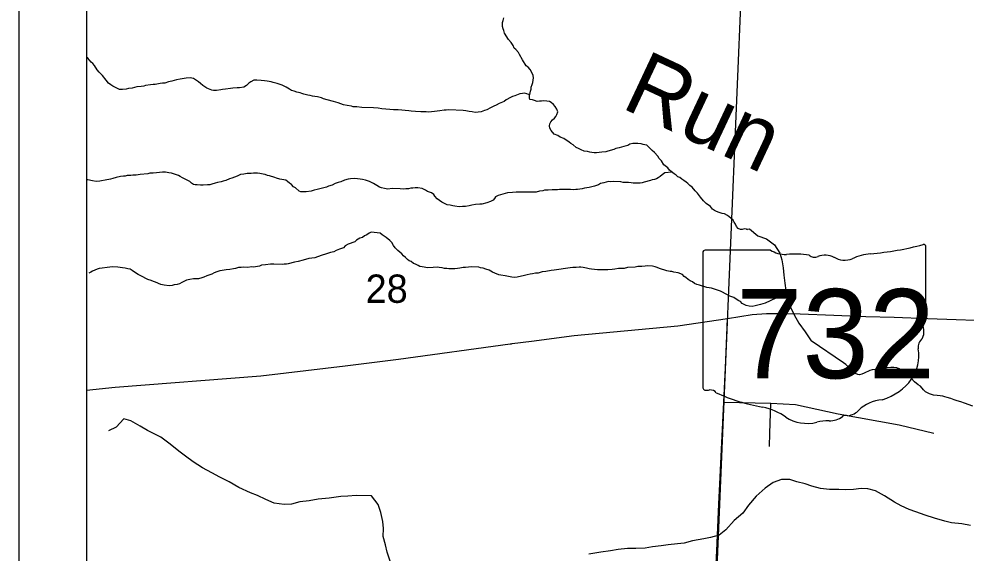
# Model space of a CAD drawing. Extents: x 0 to 34, y 0 to 22.
# Drawn here: x 2 to 3.4, y 18.922 to 19.712 of the extents above; entities that cross this region are included whole.
import ezdxf

# ---------------------------------------------------------------- set-up
doc = ezdxf.new("R2010")
doc.units = 0
for name, color, linetype in [('Default', 7, 'Continuous'), ('GM_X_City_Street', 7, 'Continuous'), ('GM_X_County_Road', 7, 'Continuous'), ('GM_X_Minor_River', 7, 'Continuous'), ('GM_X_Minor_River_Text', 7, 'Continuous'), ('GM_X_Section', 7, 'Continuous'), ('GM_X_Section_Text', 7, 'Continuous'), ('GM_X_State_Location', 7, 'Continuous'), ('GM_X_State_Route', 7, 'Continuous'), ('GM_X_State_Shield', 7, 'Continuous'), ('SH_Data', 7, 'Continuous')]:
    doc.layers.add(name, color=color, linetype=linetype)

msp = doc.modelspace()

# ---------------------------------------------------------------- linework, layer by layer
at = {"layer": 'Default'}
msp.add_lwpolyline([(6.0871, 20.9), (2.1, 20.9), (2.1, 17.8044), (2.8305, 17.7727), (2.976, 17.7664), (3.1037, 17.7609), (3.4544, 17.7458), (3.7662, 17.7368), (3.9904, 17.7296), (4.1165, 17.7286), (4.1238, 17.7269), (4.1354, 17.7264), (4.1969, 17.7246), (4.2769, 17.7222), (4.4203, 17.718), (4.506, 17.7155), (4.6237, 17.7121), (4.6735, 17.7102), (4.763, 17.7084), (4.9045, 17.7039), (4.98, 17.7015), (5.0396, 17.6997)], dxfattribs=at)
msp.add_lwpolyline([(2.1, 19.8201), (2.1, 18.8072), (3.0273, 18.7832), (3.0692, 19.7796)], close=True, dxfattribs=at)
at = {"layer": 'GM_X_City_Street'}
for points in [[(3.0419, 19.1453), (3.1112, 19.1437), (3.1478, 19.1417), (3.2111, 19.128), (3.301, 19.1116), (3.3521, 19.0995)], [(3.1095, 19.0796), (3.1098, 19.0993), (3.1106, 19.1136), (3.1112, 19.1437)]]:
    msp.add_lwpolyline(points, dxfattribs=at)
at = {"layer": 'GM_X_County_Road'}
msp.add_line((2.7281, 19.2315), (2.7291, 19.2317), dxfattribs=at)
for points in [[(2.7291, 19.2317), (2.7577, 19.2352), (2.8206, 19.2436), (2.9741, 19.2578), (3.0474, 19.269)], [(3.0474, 19.269), (3.0839, 19.2749), (3.1052, 19.2762), (3.124, 19.2763), (3.1547, 19.2758), (3.2047, 19.2738), (3.2517, 19.2718), (3.2939, 19.2706), (3.3433, 19.2687), (3.3854, 19.2673), (3.4132, 19.2664), (3.4438, 19.2649), (3.4835, 19.2641), (3.5284, 19.2621), (3.5555, 19.2612), (3.6227, 19.2594), (3.6633, 19.2574)], [(2.3952, 19.1886), (2.482, 19.1988), (2.5612, 19.2087), (2.726, 19.2313), (2.7281, 19.2315)], [(2.1, 19.163), (2.1423, 19.1675), (2.3574, 19.1842), (2.3952, 19.1886)]]:
    msp.add_lwpolyline(points, dxfattribs=at)
at = {"layer": 'GM_X_Minor_River'}
for points in [[(2.8237, 19.5216), (2.8192, 19.5256), (2.8159, 19.5276), (2.8132, 19.5296), (2.8054, 19.5348), (2.7998, 19.5369), (2.7964, 19.5393), (2.7911, 19.5414), (2.7867, 19.5469), (2.7846, 19.5504), (2.7843, 19.5535), (2.7848, 19.5569), (2.7864, 19.5595), (2.7888, 19.5628), (2.7915, 19.565), (2.7935, 19.5676), (2.7952, 19.5706), (2.7964, 19.5744), (2.795, 19.5782), (2.7925, 19.5821), (2.7903, 19.5853), (2.7866, 19.5884), (2.784, 19.5897), (2.7802, 19.5902), (2.7752, 19.5907), (2.7726, 19.5904), (2.7695, 19.5902), (2.7661, 19.5899), (2.7623, 19.5912), (2.7589, 19.592), (2.7551, 19.5926), (2.7548, 19.5952), (2.7549, 19.5983), (2.7558, 19.6024), (2.7559, 19.6051), (2.7571, 19.6081), (2.7572, 19.6108), (2.7585, 19.6149), (2.7597, 19.6179), (2.7607, 19.6247), (2.7601, 19.6282), (2.7579, 19.6325), (2.7558, 19.6371), (2.7525, 19.6403), (2.7499, 19.6426), (2.7441, 19.6512), (2.7398, 19.659), (2.7383, 19.6621), (2.7347, 19.6664), (2.7321, 19.6688), (2.7303, 19.6723), (2.7274, 19.6769), (2.7237, 19.6813), (2.7179, 19.6906), (2.7165, 19.6945), (2.7155, 19.6972), (2.7148, 19.7006), (2.7146, 19.7037), (2.715, 19.7067), (2.7155, 19.7094), (2.7168, 19.7135)], [(2.258, 19.6238), (2.2531, 19.6247), (2.2473, 19.6241), (2.2443, 19.6239), (2.2385, 19.6229), (2.2327, 19.6216), (2.2262, 19.6199), (2.2212, 19.6186), (2.2154, 19.6169), (2.2124, 19.6166), (2.2089, 19.6163), (2.2016, 19.615), (2.1982, 19.6148), (2.1943, 19.6142), (2.1871, 19.6133), (2.1844, 19.6126), (2.1805, 19.612), (2.1744, 19.6114), (2.1675, 19.6094), (2.1617, 19.6088), (2.1587, 19.6078), (2.1533, 19.6076), (2.1487, 19.6077), (2.1416, 19.611), (2.139, 19.6126), (2.1356, 19.6143), (2.1326, 19.617), (2.129, 19.6214), (2.1235, 19.6284), (2.1187, 19.6331), (2.1154, 19.6367), (2.1118, 19.6429), (2.1092, 19.6457), (2.1066, 19.6477), (2.1018, 19.6539), (2.1, 19.6553)], [(2.7554, 19.6008), (2.7534, 19.6002), (2.7508, 19.6011), (2.747, 19.602), (2.7443, 19.6017), (2.7405, 19.6011), (2.7378, 19.6), (2.7332, 19.5983), (2.7293, 19.5969), (2.7266, 19.5954), (2.7204, 19.5922), (2.7172, 19.5897), (2.7099, 19.5869), (2.7052, 19.5844), (2.7021, 19.5826), (2.6971, 19.5801), (2.6916, 19.5776), (2.6882, 19.5762), (2.6832, 19.5745), (2.6789, 19.5738), (2.6744, 19.5736), (2.6698, 19.5745), (2.6656, 19.5751), (2.6607, 19.576), (2.6565, 19.5765), (2.6356, 19.5772), (2.6317, 19.577), (2.6283, 19.5767), (2.6222, 19.5758), (2.618, 19.5756), (2.6141, 19.5749), (2.6099, 19.5743), (2.6049, 19.5737), (2.6019, 19.5742), (2.5939, 19.5745), (2.5863, 19.5751), (2.5798, 19.5754), (2.5764, 19.5759), (2.5707, 19.5764), (2.5661, 19.577), (2.5604, 19.5772), (2.5536, 19.5774), (2.5482, 19.578), (2.5425, 19.5785), (2.5365, 19.5791), (2.5311, 19.5797), (2.5239, 19.5803), (2.5068, 19.5809), (2.4992, 19.5816), (2.4942, 19.5817), (2.4916, 19.5826), (2.4851, 19.5839), (2.4798, 19.5849), (2.476, 19.5862), (2.4719, 19.5878), (2.4651, 19.5896), (2.4557, 19.5922), (2.45, 19.5939), (2.4474, 19.5952), (2.4413, 19.5965), (2.4375, 19.597), (2.4341, 19.5975), (2.4303, 19.5984), (2.4269, 19.5993), (2.4212, 19.6006), (2.4182, 19.6015), (2.4156, 19.6023), (2.411, 19.6036), (2.4069, 19.6049), (2.4031, 19.6062), (2.4001, 19.6078), (2.3949, 19.6111), (2.3889, 19.6139), (2.3817, 19.6161), (2.376, 19.6178), (2.3726, 19.6187), (2.3669, 19.62), (2.3631, 19.6205), (2.3578, 19.6207), (2.3517, 19.6213), (2.3471, 19.6211), (2.3429, 19.6189), (2.3398, 19.6168), (2.3362, 19.6135), (2.3323, 19.6109), (2.3258, 19.61), (2.3224, 19.6097), (2.3162, 19.6092), (2.3128, 19.6089), (2.3055, 19.608), (2.3009, 19.6074), (2.2982, 19.6068), (2.2921, 19.6062), (2.2875, 19.606), (2.2849, 19.6065), (2.2777, 19.6094), (2.2717, 19.6134), (2.2684, 19.6162), (2.2654, 19.6189), (2.2625, 19.6206), (2.258, 19.6238)], [(3.0775, 19.4001), (3.0752, 19.4009), (3.0725, 19.4014), (3.0691, 19.4004), (3.0664, 19.4005), (3.063, 19.4021), (3.0604, 19.4049), (3.0594, 19.4083), (3.0572, 19.4111), (3.0558, 19.4142), (3.0525, 19.4173), (3.0499, 19.4193), (3.0473, 19.4213), (3.0431, 19.4234), (3.0394, 19.4243), (3.0352, 19.4256), (3.0311, 19.4272), (3.028, 19.4285), (3.0254, 19.4305), (3.0221, 19.4344), (3.0158, 19.4388), (3.0121, 19.4427), (3.0073, 19.4482), (3.003, 19.4541), (2.9997, 19.4576), (2.9953, 19.4631), (2.9919, 19.4655), (2.9886, 19.4687), (2.986, 19.4703), (2.983, 19.4731), (2.98, 19.4747), (2.9767, 19.4771), (2.974, 19.4783), (2.9714, 19.4807), (2.9684, 19.4827), (2.964, 19.4863), (2.9614, 19.4883), (2.9592, 19.4914), (2.9533, 19.4962), (2.9496, 19.502), (2.9463, 19.5052), (2.9442, 19.5091), (2.9394, 19.5142), (2.936, 19.5174), (2.9323, 19.5209), (2.9279, 19.5249), (2.9253, 19.5257), (2.9226, 19.5262), (2.9196, 19.5271), (2.9146, 19.5276), (2.9074, 19.5275), (2.9032, 19.5265), (2.9, 19.5247), (2.8939, 19.523), (2.887, 19.521), (2.8823, 19.52), (2.8792, 19.5186), (2.8704, 19.5162), (2.8673, 19.5155), (2.8616, 19.5146), (2.8574, 19.5144), (2.8535, 19.5137), (2.8501, 19.5139), (2.8467, 19.5143), (2.844, 19.5148), (2.8402, 19.5157), (2.8357, 19.5163), (2.8308, 19.5183), (2.827, 19.52), (2.8237, 19.5216)], [(2.4868, 19.4749), (2.481, 19.4732), (2.4756, 19.4711), (2.4718, 19.4697), (2.4675, 19.4684), (2.4629, 19.4658), (2.4575, 19.4645), (2.4544, 19.4631), (2.4409, 19.4597), (2.4363, 19.4588), (2.4317, 19.457), (2.4244, 19.4561), (2.421, 19.4559), (2.4168, 19.456), (2.4141, 19.4569), (2.4086, 19.462), (2.406, 19.4636), (2.4027, 19.4672), (2.4, 19.4688), (2.3971, 19.4715), (2.3945, 19.4735), (2.3857, 19.475), (2.3808, 19.4763), (2.3782, 19.4775), (2.3706, 19.4797), (2.3676, 19.4802), (2.3639, 19.4818), (2.3612, 19.4823), (2.3563, 19.4832), (2.3525, 19.4837), (2.3498, 19.4838), (2.3467, 19.4836), (2.3433, 19.4833), (2.3372, 19.4831), (2.3326, 19.4821), (2.3276, 19.4819), (2.3226, 19.4791), (2.3145, 19.4763), (2.3114, 19.4753), (2.3056, 19.4728), (2.3021, 19.4718), (2.299, 19.4707), (2.2937, 19.4698), (2.2902, 19.4688), (2.2852, 19.4674), (2.2821, 19.4667), (2.2787, 19.4665), (2.2725, 19.4659), (2.2684, 19.4661), (2.2634, 19.4666), (2.2607, 19.4667), (2.2581, 19.4672), (2.2551, 19.4688), (2.2525, 19.4712), (2.2416, 19.4769), (2.2383, 19.4789), (2.2356, 19.4802), (2.23, 19.4823), (2.2255, 19.4836), (2.2217, 19.4844), (2.2167, 19.4854), (2.2122, 19.4852), (2.2034, 19.4843), (2.1984, 19.4837), (2.1934, 19.4835), (2.1903, 19.4829), (2.1792, 19.4817), (2.1735, 19.4808), (2.1685, 19.4806), (2.1655, 19.4803), (2.1601, 19.4801), (2.157, 19.4794), (2.1544, 19.4791), (2.1502, 19.4789), (2.1436, 19.4772), (2.139, 19.4759), (2.1351, 19.4749), (2.1275, 19.4732), (2.1221, 19.4726), (2.1194, 19.472), (2.1141, 19.4714), (2.1087, 19.4723), (2.1019, 19.4737), (2.1, 19.474)], [(2.9652, 19.4853), (2.9548, 19.4843), (2.9509, 19.4814), (2.9477, 19.4789), (2.945, 19.4767), (2.9423, 19.4756), (2.9392, 19.4746), (2.9361, 19.4739), (2.9334, 19.4729), (2.9242, 19.4702), (2.9211, 19.4695), (2.9184, 19.4692), (2.9134, 19.469), (2.9077, 19.4692), (2.9047, 19.4693), (2.9009, 19.4698), (2.8933, 19.4701), (2.8899, 19.471), (2.8784, 19.4713), (2.8742, 19.4711), (2.8716, 19.4712), (2.8681, 19.4706), (2.8643, 19.4695), (2.8596, 19.4686), (2.8569, 19.4664), (2.8538, 19.4657), (2.8507, 19.4643), (2.8431, 19.4627), (2.8358, 19.4614), (2.8323, 19.4604), (2.8258, 19.4594), (2.8231, 19.4595), (2.8204, 19.4592), (2.8151, 19.4594), (2.8059, 19.4594), (2.7991, 19.4596), (2.796, 19.4593), (2.7884, 19.4592), (2.7823, 19.4587), (2.7769, 19.4585), (2.7742, 19.4578), (2.7696, 19.4572), (2.7646, 19.4558), (2.7574, 19.4557), (2.7528, 19.4555), (2.7444, 19.4558), (2.7406, 19.4555), (2.7349, 19.4557), (2.7295, 19.4551), (2.7223, 19.4546), (2.7188, 19.4536), (2.7084, 19.4509), (2.7045, 19.4488), (2.7029, 19.4462), (2.7009, 19.4436), (2.697, 19.4418), (2.6916, 19.4401), (2.6843, 19.438), (2.6813, 19.4378), (2.6748, 19.4372), (2.6694, 19.4363), (2.6655, 19.4356), (2.6602, 19.4343), (2.6556, 19.4344), (2.6506, 19.4342), (2.6445, 19.4348), (2.6411, 19.4353), (2.6373, 19.4362), (2.6332, 19.4371), (2.629, 19.4388), (2.6249, 19.4408), (2.6182, 19.446), (2.6149, 19.4496), (2.6135, 19.4523), (2.6097, 19.4547), (2.6041, 19.4568), (2.6011, 19.4588), (2.5958, 19.4613), (2.5894, 19.4623), (2.5856, 19.462), (2.5821, 19.4617), (2.5791, 19.4615), (2.576, 19.4608), (2.5718, 19.4606), (2.5683, 19.4603), (2.5634, 19.4605), (2.5516, 19.4609), (2.5455, 19.4603), (2.5402, 19.4613), (2.536, 19.4622), (2.533, 19.4631), (2.5292, 19.4655), (2.524, 19.4687), (2.5184, 19.4712), (2.5123, 19.4733), (2.5078, 19.4742), (2.5044, 19.4747), (2.5006, 19.4756), (2.496, 19.4761), (2.4899, 19.4752), (2.4868, 19.4749)], [(2.6015, 19.3441), (2.5988, 19.3446), (2.5958, 19.3451), (2.5927, 19.3459), (2.5901, 19.3472), (2.586, 19.3492), (2.5834, 19.3501), (2.5796, 19.3529), (2.577, 19.3541), (2.5744, 19.3561), (2.5714, 19.3589), (2.5685, 19.3613), (2.5659, 19.3644), (2.5629, 19.3668), (2.56, 19.3695), (2.5559, 19.3735), (2.5534, 19.377), (2.5512, 19.3813), (2.5483, 19.3844), (2.5427, 19.3884), (2.5367, 19.3924), (2.5337, 19.3948), (2.5204, 19.3964), (2.5177, 19.395), (2.5142, 19.3925), (2.5107, 19.3911), (2.5076, 19.3885), (2.5037, 19.3875), (2.4991, 19.3846), (2.4963, 19.3824), (2.4867, 19.3789), (2.482, 19.3764), (2.4796, 19.3735), (2.4738, 19.3714), (2.4688, 19.3696), (2.4653, 19.3675), (2.4607, 19.3665), (2.453, 19.3641), (2.4484, 19.3623), (2.4414, 19.3599), (2.4372, 19.3585), (2.433, 19.3583), (2.4284, 19.3577), (2.4203, 19.3553), (2.4126, 19.3533), (2.4072, 19.3519), (2.398, 19.3496), (2.3953, 19.3493), (2.3918, 19.349), (2.3892, 19.3488), (2.3766, 19.3492), (2.372, 19.349), (2.3643, 19.3481), (2.3586, 19.3475), (2.3555, 19.3461), (2.3467, 19.3449), (2.3436, 19.345), (2.3383, 19.3444), (2.3314, 19.3447), (2.3284, 19.3444), (2.3245, 19.3441), (2.3199, 19.3428), (2.3172, 19.3421), (2.3115, 19.3412), (2.3065, 19.3409), (2.3004, 19.3396), (2.2969, 19.3394), (2.2923, 19.338), (2.2888, 19.3362), (2.2849, 19.3344), (2.2776, 19.332), (2.2733, 19.3299), (2.2703, 19.3289), (2.2656, 19.3275), (2.2618, 19.3276), (2.258, 19.3274), (2.2526, 19.3264), (2.2476, 19.3254), (2.2449, 19.324), (2.2407, 19.3219), (2.2372, 19.3201), (2.2341, 19.3191), (2.2295, 19.3184), (2.2264, 19.3178), (2.2222, 19.3172), (2.2146, 19.3182), (2.2097, 19.3191), (2.2018, 19.3224), (2.1988, 19.3237), (2.1954, 19.325), (2.1904, 19.3263), (2.1878, 19.3279), (2.183, 19.3307), (2.1762, 19.334), (2.171, 19.3376), (2.1676, 19.3396), (2.1643, 19.3416), (2.1612, 19.3425), (2.1571, 19.3434), (2.1529, 19.3439), (2.1464, 19.3449)], [(3.0752, 19.4009), (3.0801, 19.4013), (3.0924, 19.3911), (3.1051, 19.3867), (3.117, 19.3776), (3.1247, 19.3653), (3.1275, 19.3558), (3.1294, 19.3439), (3.1307, 19.3329), (3.1319, 19.3211), (3.1335, 19.3101), (3.1359, 19.3002), (3.1401, 19.2864), (3.1459, 19.2745), (3.1528, 19.2618), (3.1623, 19.249), (3.1711, 19.2359)], [(2.1464, 19.3449), (2.1384, 19.3452), (2.1304, 19.3443), (2.1231, 19.3434), (2.1185, 19.3428), (2.1158, 19.3418), (2.1089, 19.339), (2.1061, 19.3372), (2.1034, 19.3361)], [(3.1345, 19.3062), (3.1028, 19.2914), (3.0959, 19.2897), (3.0882, 19.2877), (3.0836, 19.2867), (3.0794, 19.2869), (3.0749, 19.2882), (3.0692, 19.291), (3.0666, 19.2938), (3.0629, 19.2955), (3.0569, 19.2999), (3.0509, 19.302), (3.0475, 19.304), (3.037, 19.3093), (3.0325, 19.3106), (3.0238, 19.3136), (3.0166, 19.3146), (3.006, 19.318), (3.0019, 19.3193), (2.9985, 19.3205), (2.9955, 19.3229), (2.9922, 19.3246), (2.9892, 19.3266), (2.9858, 19.3297), (2.9832, 19.331), (2.9806, 19.3341), (2.9746, 19.3366), (2.9682, 19.3376), (2.9651, 19.3381), (2.9625, 19.3385), (2.9576, 19.3395), (2.947, 19.3429), (2.9436, 19.3445), (2.9402, 19.3454), (2.9364, 19.3463), (2.9292, 19.3465), (2.9257, 19.3463), (2.9208, 19.3457), (2.915, 19.3455), (2.9108, 19.3449), (2.8994, 19.3441), (2.8944, 19.3428), (2.8863, 19.3427), (2.881, 19.3417), (2.8768, 19.3415), (2.8706, 19.3409), (2.8661, 19.3407), (2.8584, 19.341), (2.855, 19.3407), (2.8463, 19.3418), (2.8428, 19.3423), (2.8391, 19.3432), (2.8341, 19.3441), (2.8307, 19.3446), (2.8281, 19.3447), (2.8235, 19.3445), (2.8189, 19.3442), (2.815, 19.3436), (2.8043, 19.3425), (2.8016, 19.3418), (2.7913, 19.3402), (2.7867, 19.3396), (2.7786, 19.3384), (2.7733, 19.3378), (2.7702, 19.3368), (2.7675, 19.3361), (2.7633, 19.3359), (2.7591, 19.3349), (2.7556, 19.3342), (2.751, 19.3332), (2.7472, 19.3322), (2.7364, 19.3299), (2.7318, 19.3297), (2.7284, 19.3302), (2.7235, 19.3311), (2.7185, 19.3317), (2.7125, 19.3327), (2.7094, 19.3335), (2.7034, 19.336), (2.7, 19.3373), (2.6952, 19.3401), (2.6899, 19.3418), (2.6861, 19.3431), (2.6823, 19.344), (2.6797, 19.3448), (2.669, 19.3452), (2.6602, 19.3444), (2.6568, 19.3441), (2.6518, 19.3431), (2.648, 19.3429), (2.6441, 19.3423), (2.6415, 19.3424), (2.6353, 19.3422), (2.6327, 19.3427), (2.6289, 19.3428), (2.6255, 19.3437), (2.6213, 19.3442), (2.6183, 19.3447), (2.6122, 19.3445), (2.6045, 19.344), (2.6015, 19.3441)], [(3.4098, 19.1394), (3.3977, 19.1435), (3.3924, 19.1455), (3.3867, 19.1472), (3.3822, 19.1488), (3.3773, 19.1505), (3.372, 19.1521), (3.3686, 19.153), (3.3656, 19.1538), (3.3618, 19.1547), (3.3573, 19.1552), (3.3516, 19.1557), (3.3459, 19.1577), (3.3399, 19.1605), (3.3369, 19.1633), (3.3325, 19.1687), (3.3291, 19.171), (3.3239, 19.1754), (3.3187, 19.1804), (3.3145, 19.1828), (3.3097, 19.1879), (3.3071, 19.1902), (3.3041, 19.1922), (3.3011, 19.1945), (3.2974, 19.1961), (3.2932, 19.1966), (3.2886, 19.1964), (3.2833, 19.1957), (3.2764, 19.1948), (3.2711, 19.1945), (3.2657, 19.1935), (3.2612, 19.1929), (3.2577, 19.1922), (3.2493, 19.1879), (3.2458, 19.1864), (3.2424, 19.1854), (3.2401, 19.1858), (3.2341, 19.1886), (3.2311, 19.1917), (3.2289, 19.1944), (3.2222, 19.2007), (3.2188, 19.2034), (3.1711, 19.2359)], [(2.3774, 18.9959), (2.365, 19.0011), (2.3526, 19.0071), (2.3421, 19.0112), (2.3252, 19.0192), (2.3106, 19.0275), (2.2971, 19.0343), (2.2851, 19.0407), (2.2712, 19.0479), (2.2574, 19.0569), (2.2462, 19.0652), (2.2365, 19.0727), (2.2235, 19.0829), (2.2097, 19.0935), (2.1902, 19.1034), (2.1794, 19.1094), (2.1652, 19.1173), (2.155, 19.1203), (2.1437, 19.1084), (2.1325, 19.1026)], [(3.4064, 18.9629), (3.3936, 18.9651), (3.3784, 18.9666), (3.3686, 18.9691), (3.3531, 18.9737), (3.3396, 18.9782), (3.3257, 18.9831), (3.3159, 18.9864), (3.3042, 18.992), (3.2941, 18.9972), (3.2796, 19.0067), (3.2661, 19.0138), (3.2548, 19.0172), (3.2449, 19.0174), (3.2335, 19.0158), (3.2217, 19.0153), (3.2118, 19.0159), (3.1981, 19.0159), (3.1849, 19.0177), (3.1721, 19.0211), (3.1619, 19.0244), (3.1498, 19.0273), (3.1393, 19.0306), (3.1271, 19.0306), (3.1149, 19.0263), (3.1029, 19.0179), (3.0897, 19.006), (3.0783, 18.9926), (3.07, 18.9811), (3.0572, 18.97), (3.0447, 18.9562), (3.035, 18.9485), (3.022, 18.945), (3.0125, 18.943), (2.9957, 18.9403), (2.9834, 18.9365), (2.9735, 18.9356), (2.9598, 18.934), (2.9492, 18.9327), (2.9366, 18.9312), (2.9255, 18.9292), (2.9119, 18.9287), (2.8993, 18.9287), (2.8856, 18.9275), (2.8742, 18.9255), (2.8601, 18.9235), (2.8425, 18.9206)], [(2.549, 18.9084), (2.5445, 18.9233), (2.5417, 18.9344), (2.5386, 18.9467), (2.5389, 18.9584), (2.5377, 18.9687), (2.535, 18.9821), (2.5311, 18.994), (2.5212, 19.0064), (2.4984, 19.0069), (2.4862, 19.0061), (2.4756, 19.0056), (2.4584, 19.0034), (2.4421, 19.0015), (2.4291, 18.9991), (2.4154, 18.9976), (2.4028, 18.9945), (2.3921, 18.9936), (2.3774, 18.9959)]]:
    msp.add_lwpolyline(points, dxfattribs=at)
at = {"layer": 'GM_X_Section'}
msp.add_lwpolyline([(3.0692, 19.7796), (4.0623, 19.7415), (4.0218, 18.7461), (3.0273, 18.7832)], close=True, dxfattribs=at)
at = {"layer": 'GM_X_State_Route'}
for points in [[(3.0248, 18.7867), (3.0253, 18.7987), (3.0277, 18.848), (3.0314, 18.9253), (3.0324, 18.9483), (3.0344, 18.9941), (3.0363, 19.0344), (3.0384, 19.0751), (3.0419, 19.1453), (3.0445, 19.1957), (3.0461, 19.2315), (3.0474, 19.269)], [(3.0474, 19.269), (3.0839, 19.2749), (3.1052, 19.2762), (3.124, 19.2763), (3.1547, 19.2758), (3.2047, 19.2738), (3.2517, 19.2718), (3.2939, 19.2706), (3.3433, 19.2687), (3.3854, 19.2673), (3.4132, 19.2664), (3.4438, 19.2649), (3.4835, 19.2641), (3.5284, 19.2621), (3.5555, 19.2612), (3.6227, 19.2594), (3.6633, 19.2574)]]:
    msp.add_lwpolyline(points, dxfattribs=at)
at = {"layer": 'GM_X_State_Shield'}
for p, q in [((3.011, 19.3665), (3.011, 19.1664)), ((3.1108, 19.3699), (3.0143, 19.3699)), ((3.3406, 19.2702), (3.3406, 19.3749)), ((3.3406, 19.2702), (3.3406, 19.2702))]:
    msp.add_line(p, q, dxfattribs=at)
for centre, major_axis, start_param, end_param in [((3.2232, 19.6428), (0.3495, 0), 4.814394, 5.042369), ((3.337, 19.3753), (0.00367, 0), 6.141152, 7.989035), ((3.0148, 19.3669), (0.00382, 0), 1.712693, 3.28349), ((3.1338, 19.3932), (0.037, 0), 4.042523, 4.731795), ((3.1461, 19.2576), (0.133, 0), 1.404758, 1.657858), ((3.1763, 19.368), (0.0107, 0), 3.836095, 5.185415), ((3.1919, 19.3448), (0.0222, 0), 0.950623, 2.079405), ((3.2678, 19.3088), (0.0703, 0), 1.699011, 2.107814), ((3.2206, 19.3766), (0.0267, 0), 4.081561, 5.145723), ((3.3398, 19.2625), (0.00568, 0), 1.883978, 3.671073), ((3.3367, 19.2698), (0.00393, 0), 5.05454, 6.418171), ((3.3037, 19.2493), (0.0341, 0), 5.934695, 6.695948), ((3.3538, 19.2264), (0.0248, 0), 2.387724, 3.262537), ((3.2428, 19.2131), (0.0874, 0), 5.101752, 6.440018), ((3.0149, 19.1659), (0.00385, 0), 3.00124, 4.508301), ((3.0154, 19.1864), (0.0294, 0), 4.665946, 4.897461), ((3.0215, 19.1548), (0.0106, 0), 0.519207, 1.627899), ((3.1553, 19.3346), (0.2524, 0), 4.195997, 4.488961), ((3.08, 19.0765), (0.079, 0), 0.823519, 1.323587), ((3.2797, 19.1102), (0.0479, 0), 1.647645, 2.488434), ((3.1981, 19.1389), (0.0267, 0), 4.691044, 5.507374), ((3.2222, 19.1195), (0.00752, 0), 1.147584, 2.315152), ((3.219, 19.147), (0.0282, 0), 4.937069, 5.64225), ((3.1654, 19.1538), (0.0501, 0), 4.026481, 4.996735), ((3.1944, 19.0846), (0.0412, 0), 1.495662, 1.94098)]:
    msp.add_ellipse(centre, major_axis=major_axis, ratio=0.8, start_param=start_param, end_param=end_param, dxfattribs=at)
at = {"layer": 'SH_Data'}
for p, q in [((2, 21), (2, 14)), ((2.1, 20.9), (2.1, 14.1))]:
    msp.add_line(p, q, dxfattribs=at)

# ---------------------------------------------------------------- texts
at = {"layer": 'GM_X_Minor_River_Text'}
msp.add_text('Run', height=0.09469, rotation=334.8755, dxfattribs=at).set_placement((2.8882, 19.5813))
at = {"layer": 'GM_X_Section_Text'}
msp.add_text('28', height=0.04186, rotation=0, dxfattribs=at).set_placement((2.5124, 19.292))
at = {"layer": 'GM_X_State_Location'}
for s in ['s', 'r']:
    msp.add_text(s, height=0.000189, dxfattribs=at).set_placement((3.1721, 19.2531))
msp.add_text('732', height=0.000189, rotation=0, dxfattribs=at).set_placement((3.1053, 19.2394))
at = {"layer": 'GM_X_State_Shield'}
msp.add_text('732', height=0.13184, dxfattribs=at).set_placement((3.06, 19.1805))

doc.saveas('drawing.dxf')
